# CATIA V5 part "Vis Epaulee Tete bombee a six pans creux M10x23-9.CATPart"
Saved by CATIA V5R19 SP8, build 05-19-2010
Part number: Vis Epaulée Tetebombee a six pan creux M10x23-9
Nomenclature: 18
Source: Unknown
Description: PART-screw_gb_t_70_2_m10x25-DESC
Bounding box of the stored display mesh (mm): x -5.5 to 23, y -8.743 to 8.75, z -8.75 to 8.75
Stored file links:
  C:\Users\rphgr\Desktop\0_Tapis_TC520B_vitesse\Vis Epaulee Tete bombee a six pans creux M10x23-9.CATPart
  C:\Program Files\Dassault Systemes\B19\win_b64\reffiles\standard\MetricThickPitch.txt
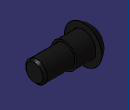
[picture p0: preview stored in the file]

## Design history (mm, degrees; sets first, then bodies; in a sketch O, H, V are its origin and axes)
AxisSystem1: origin (0, 0, 0), X (1, 0, 0), Y (0, 1, 0), Z (0, 0, 1)
Body1 "screw_gb_t_70_2_m10x25" (main body)
  Solid1: solid without history
  Thickness1: Thickness 0.5, Face (face of Solid1; face of Solid1; face of Solid1; face of Solid1; face of Solid1; face of Solid1)
  Sketch1 on ZX plane of AxisSystem1, origin (0, 0, 0), H (0, 0, 1), V (1, 0, 0)
    arc A1 centre (0, 3.1669) radius 9.3055 from (8.75, 0) to (3.3876, -5.5) cw
    point P1 (0, 3.1669)
    point P2 (8.75, 0)
    point P3 (3.3876, -5.5)
    reference projected line E1 through (0, 0) direction (0, 1) from axis of face of Solid1
    reference intersected line E2 through (0, -5.5) direction (1, 0) from face of Solid1
    reference intersected line E3 (2.8876, -5.5) -> (2.8876, -2.0477) from face of Solid1
    reference projected line E4 through (0, 0) direction (0, 1) from axis of face of Solid1
    distance P3 E3 = 0.5
    distance P2 E4 = 8.75
    coincidence: P2 H, P1 E1, P3 E2
  Groove1: profile Sketch1, axis axis of face of Solid1, angle 360
  Split1: SplitPlane face of Solid1
  Sketch2 on ZX plane of AxisSystem1, origin (0, 0, 0), H (0, 0, 1), V (1, 0, 0)
    point P1 (-6, 0)
    line L1 (-6, 0) -> (-6, 9)
    line L2 (-6, 9) -> (-5, 9)
    line L3 (-5, 9) -> (-5, 23)
    line L4 (-5, 23) -> (0, 23)
    point P5 (0, 23)
    axis line L5 (0, -7.7284) -> (0, 34.7223)
    point P6 (0, -7.7284)
    reference intersected line E1 (-8.75, 0) -> (8.75, 0) from face of Split1
    reference intersected line E2 (-8.75, 0) -> (8.75, 0) from face of Split1
    distance L5 L1 = 6
    distance L3 L5 = 5
    distance L2 E1 = 9
    distance L4 E2 = 23
    coincidence: P1 H, P5 V, P6 V
    vertical: L1 V, L3 V, L5 V
    horizontal: L2 H, L4 H
  Shaft1: profile Sketch2, axis Sketch2.L5, angle 360
  Thread1: "M10", diameter 10, depth 14, pitch 1.5, on face of Shaft1 from Sketch2.L3, from face of Shaft1 from Sketch2.L4
  Chamfer1: length 1, angle 45, on edge [face of Shaft1 from Sketch2.L3 | face of Shaft1 from Sketch2.L4]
